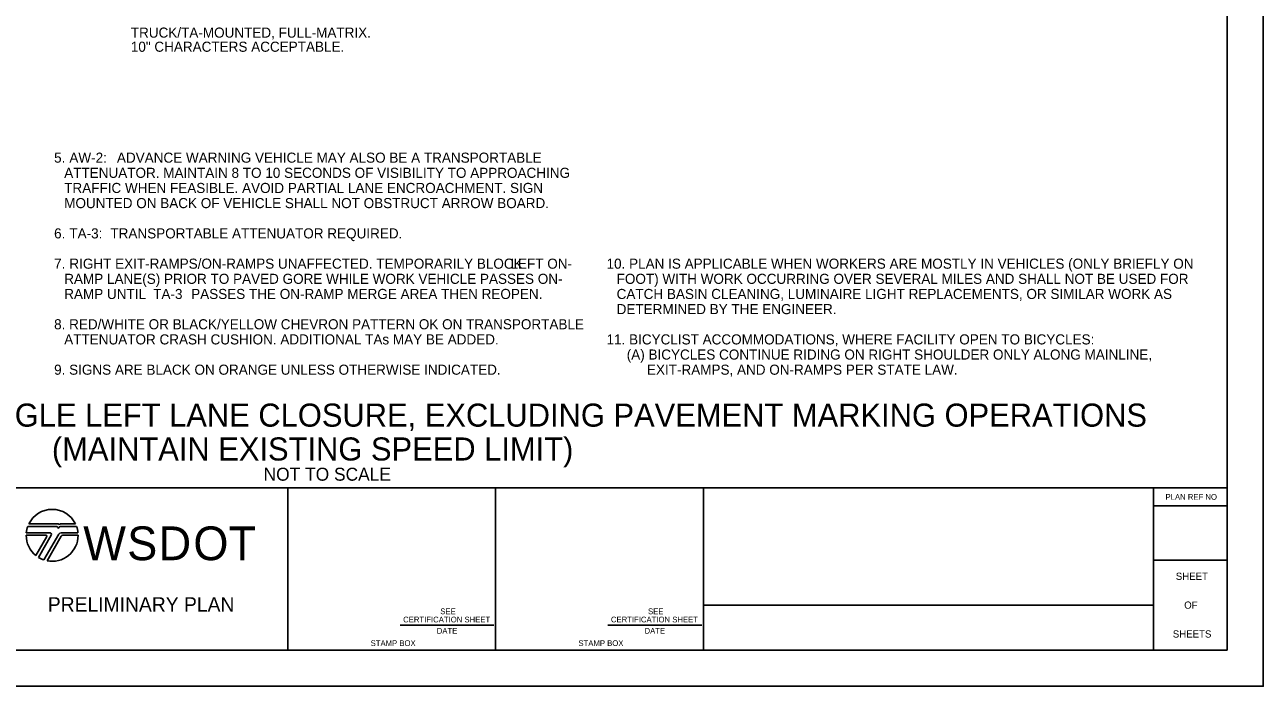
# Model space of a CAD drawing. Extents: x 0 to 17, y 0 to 11.
# Drawn here: x 8.42 to 17, y 0 to 4.59 of the extents above; entities that cross this region are included whole.
import ezdxf

# ---------------------------------------------------------------- set-up
doc = ezdxf.new("R2010")
doc.units = 0
for name, color, linetype in [('SH_GI_Logo_WSDOT', 7, 'Continuous'), ('SH_GI_PlotLimits', 7, 'Continuous'), ('SH_GI_SheetBorder1', 7, 'Continuous'), ('SH_GI_SheetBorder2', 7, 'Continuous'), ('SH_GI_SheetBorder3', 7, 'Continuous'), ('SH_GI_SheetTextInCells', 7, 'Continuous'), ('SH_GI_TitleBlockPrelimText', 7, 'Continuous'), ('TR_WZ_PortableChangeMessageSign', 7, 'Continuous'), ('TR_WZ_WorkZoneTextCurrent', 7, 'Continuous')]:
    doc.layers.add(name, color=color, linetype=linetype)

msp = doc.modelspace()

# ---------------------------------------------------------------- linework, layer by layer
at = {"layer": 'SH_GI_Logo_WSDOT'}
for p, q in [((8.6489, 1.1258), (8.4454, 1.1258)), ((8.7684, 1.1258), (8.6653, 1.1258)), ((8.4269, 1.0463), (8.5657, 1.0463)), ((8.59, 1.0643), (8.4278, 1.0643)), ((8.4377, 1.1078), (8.6354, 1.1078)), ((8.5709, 1.0373), (8.4948, 0.9054)), ((8.5121, 0.8933), (8.6004, 1.0463)), ((8.6541, 1.0553), (8.5502, 0.8754)), ((8.5713, 0.8698), (8.6697, 1.0403)), ((8.786, 1.0643), (8.6697, 1.0643)), ((8.6705, 1.1078), (8.776, 1.1078)), ((8.6801, 1.0463), (8.7869, 1.0463))]:
    msp.add_line(p, q, dxfattribs=at)
for centre, radius, start, end in [((8.6069, 1.0463), 0.18, 26.21027, 153.78973), ((8.6489, 1.1198), 0.006, 0, 90), ((8.6653, 1.1138), 0.012, 90, 150), ((8.6069, 1.0463), 0.18, 180, 231.49627), ((8.6069, 1.0463), 0.18, 160.02155, 174.26083), ((8.5657, 1.0403), 0.006, 330, 90), ((8.6069, 1.0463), 0.18, 258.58993, 0), ((8.59, 1.0523), 0.012, 330, 90), ((8.6354, 1.0943), 0.0135, 360, 90), ((8.6705, 1.0838), 0.024, 90.00001, 154.05552), ((8.6697, 1.0463), 0.018, 90, 150), ((8.6801, 1.0343), 0.012, 90, 150), ((8.6069, 1.0463), 0.18, 5.73917, 19.97845), ((8.6069, 1.0463), 0.18, 238.21167, 251.66132)]:
    msp.add_arc(centre, radius, start, end, dxfattribs=at)
at = {"layer": 'SH_GI_PlotLimits'}
msp.add_lwpolyline([(0, 11), (17, 11), (17, 0), (0, 0)], close=True, dxfattribs=at)
at = {"layer": 'SH_GI_SheetBorder1'}
for p, q in [((11.0184, 0.4233), (11.6683, 0.4233)), ((12.4584, 0.4233), (13.1083, 0.4233))]:
    msp.add_line(p, q, dxfattribs=at)
at = {"layer": 'SH_GI_SheetBorder2'}
msp.add_line((13.12, 0.5625), (16.24, 0.5625), dxfattribs=at)
at = {"layer": 'SH_GI_SheetBorder3'}
for p, q in [((16.75, 10.75), (16.75, 0.25)), ((1, 1.375), (16.75, 1.375)), ((10.24, 1.375), (10.24, 0.25)), ((11.68, 1.3759), (11.68, 0.25)), ((13.12, 1.3759), (13.12, 0.25)), ((16.24, 1.375), (16.24, 0.25)), ((16.24, 1.25), (16.75, 1.25)), ((16.24, 0.875), (16.75, 0.875)), ((1, 0.25), (16.75, 0.25))]:
    msp.add_line(p, q, dxfattribs=at)

# ---------------------------------------------------------------- texts
at = {"layer": 'SH_GI_Logo_WSDOT'}
for s, p in [('W', (8.8225, 0.8739)), ('S', (9.1268, 0.8739)), ('D', (9.3442, 0.8739)), ('O', (9.5854, 0.8739)), ('T', (9.8296, 0.8739))]:
    msp.add_text(s, height=0.234, dxfattribs=at).set_placement(p)
at = {"layer": 'SH_GI_SheetTextInCells'}
for s, height, p in [('PLAN REF NO', 0.04, (16.3228, 1.2925)), ('SHEET', 0.05, (16.394, 0.7375)), ('SEE', 0.04, (11.2966, 0.4995)), ('SEE', 0.04, (12.7366, 0.4995)), ('OF', 0.05, (16.4521, 0.5375)), ('CERTIFICATION SHEET', 0.04, (11.0393, 0.4425)), ('CERTIFICATION SHEET', 0.04, (12.4793, 0.4425)), ('DATE', 0.04, (11.2723, 0.3641)), ('DATE', 0.04, (12.7123, 0.3641)), ('SHEETS', 0.05, (16.3733, 0.3375)), ('STAMP BOX', 0.04, (10.8141, 0.2786)), ('STAMP BOX', 0.04, (12.2541, 0.2786))]:
    msp.add_text(s, height=height, dxfattribs=at).set_placement(p)
at = {"layer": 'SH_GI_TitleBlockPrelimText'}
msp.add_text('PRELIMINARY PLAN', height=0.1, dxfattribs=at).set_placement((8.5768, 0.5173))
at = {"layer": 'TR_WZ_PortableChangeMessageSign'}
for s, p in [('TRUCK/TA-MOUNTED, FULL-MATRIX.', (9.152, 4.4968)), ('10" CHARACTERS ACCEPTABLE.', (9.152, 4.3988))]:
    msp.add_text(s, height=0.07, rotation=360, dxfattribs=at).set_placement(p)
at = {"layer": 'TR_WZ_WorkZoneTextCurrent'}
for s, height, p in [('5. ', 0.07, (8.6204, 3.6297)), ('AW-2:', 0.07, (8.7261, 3.6297)), (' ADVANCE WARNING VEHICLE MAY ALSO BE A TRANSPORTABLE ', 0.07, (9.0297, 3.6297)), ('ATTENUATOR. MAINTAIN 8 TO 10 SECONDS OF VISIBILITY TO APPROACHING ', 0.07, (8.6904, 3.5247)), ('TRAFFIC WHEN FEASIBLE. AVOID PARTIAL LANE ENCROACHMENT. SIGN ', 0.07, (8.6904, 3.4197)), ('MOUNTED ON BACK OF VEHICLE SHALL NOT OBSTRUCT ARROW BOARD.', 0.07, (8.6904, 3.3147)), ('6. ', 0.07, (8.6204, 3.1047)), ('TA-3:', 0.07, (8.7261, 3.1047)), (' TRANSPORTABLE ATTENUATOR REQUIRED.', 0.07, (8.9846, 3.1047)), ('7. ', 0.07, (8.6204, 2.8947)), ('RIGHT EXIT-RAMPS/ON-RAMPS UNAFFECTED. TEMPORARILY BLOCK ', 0.07, (8.7261, 2.8947)), ('LEFT ON-', 0.07, (11.7835, 2.8947)), ('10. PLAN IS APPLICABLE WHEN WORKERS ARE MOSTLY IN VEHICLES (ONLY BRIEFLY ON ', 0.07, (12.449, 2.8947)), ('RAMP LANE(S) PRIOR TO PAVED GORE WHILE WORK VEHICLE PASSES ON-', 0.07, (8.6904, 2.7897)), ('FOOT) WITH WORK OCCURRING OVER SEVERAL MILES AND SHALL NOT BE USED FOR ', 0.07, (12.519, 2.7897)), ('RAMP UNTIL ', 0.07, (8.6904, 2.6847)), ('TA-3', 0.07, (9.3072, 2.6847)), (' PASSES THE ON-RAMP MERGE AREA THEN REOPEN.', 0.07, (9.5444, 2.6847)), ('CATCH BASIN CLEANING, LUMINAIRE LIGHT REPLACEMENTS, OR SIMILAR WORK AS ', 0.07, (12.519, 2.6847)), ('DETERMINED BY THE ENGINEER.', 0.07, (12.519, 2.5797)), ('8. RED/WHITE OR BLACK/YELLOW CHEVRON PATTERN OK ON TRANSPORTABLE ', 0.07, (8.6204, 2.4747)), ('ATTENUATOR CRASH CUSHION. ADDITIONAL TAs MAY BE ADDED.', 0.07, (8.6904, 2.3697)), ('11. BICYCLIST ACCOMMODATIONS, WHERE FACILITY OPEN TO BICYCLES:', 0.07, (12.449, 2.3697)), ('(A) BICYCLES CONTINUE RIDING ON RIGHT SHOULDER ONLY ALONG MAINLINE,   ', 0.07, (12.589, 2.2647)), ('9. SIGNS ARE BLACK ON ORANGE UNLESS OTHERWISE INDICATED.', 0.07, (8.6204, 2.1597)), ('EXIT-RAMPS, AND ON-RAMPS PER STATE LAW.', 0.07, (12.729, 2.1597)), ('FREEWAY (2+ LANES): MOBILE SINGLE LEFT LANE CLOSURE, EXCLUDING PAVEMENT MARKING OPERATIONS', 0.16, (4.7391, 1.7997)), ('(MAINTAIN EXISTING SPEED LIMIT)', 0.16, (8.6051, 1.565)), ('NOT TO SCALE', 0.09, (10.0722, 1.425))]:
    msp.add_text(s, height=height, rotation=360, dxfattribs=at).set_placement(p)

doc.saveas('drawing.dxf')
